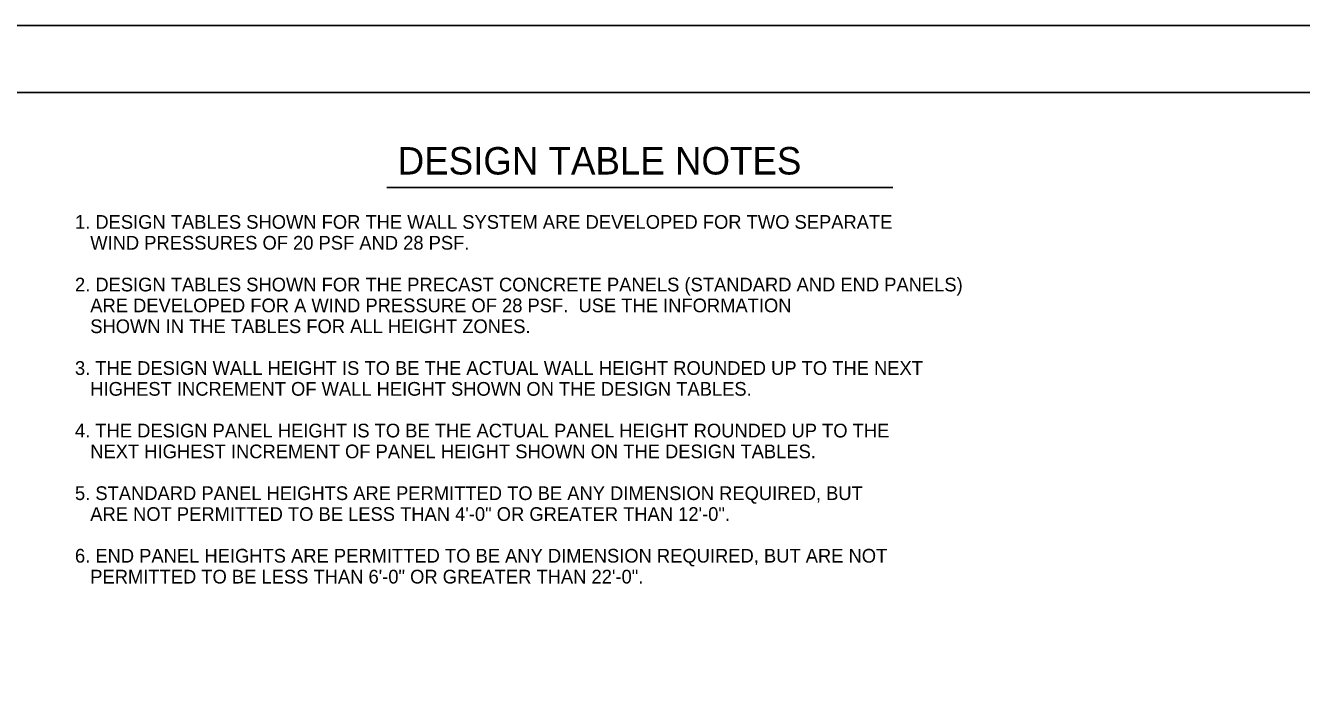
# Model space of a CAD drawing. Extents: x 3385 to 6532, y -616 to 1166.
# Drawn here: x 4106 to 4391.8, y 1016.6 to 1165.7 of the extents above; entities that cross this region are included whole.
import ezdxf

# ---------------------------------------------------------------- set-up
doc = ezdxf.new("R2010")
doc.units = 0
for name, color, linetype in [('1', 7, 'Continuous'), ('2', 7, 'Continuous'), ('PLT-BNDY', 7, 'Continuous')]:
    doc.layers.add(name, color=color, linetype=linetype)

msp = doc.modelspace()

# ---------------------------------------------------------------- linework, layer by layer
at = {"layer": '1'}
msp.add_line((4186.96, 1129.45), (4300.27, 1129.45), dxfattribs=at)
at = {"layer": '2'}
msp.add_line((3801.34, 1150.69), (4587.34, 1150.69), dxfattribs=at)
at = {"layer": 'PLT-BNDY'}
msp.add_lwpolyline([(3761.34, 1165.69), (4602.34, 1165.69), (4602.34, 571.69), (3761.34, 571.69)], close=True, dxfattribs=at)

# ---------------------------------------------------------------- texts
at = {"layer": '1'}
for s, height, p in [('DESIGN TABLE NOTES', 6.1441, (4189.36, 1132.33)), ('1. DESIGN TABLES SHOWN FOR THE WALL SYSTEM ARE DEVELOPED FOR TWO SEPARATE', 3.072, (4117.08, 1120.17)), ('   WIND PRESSURES OF 20 PSF AND 28 PSF.', 3.072, (4117.08, 1115.5)), ('2. DESIGN TABLES SHOWN FOR THE PRECAST CONCRETE PANELS (STANDARD AND END PANELS)', 3.072, (4117.08, 1106.15)), ('   ARE DEVELOPED FOR A WIND PRESSURE OF 28 PSF.  USE THE INFORMATION', 3.072, (4117.08, 1101.48)), ('   SHOWN IN THE TABLES FOR ALL HEIGHT ZONES.', 3.072, (4117.08, 1096.81)), ('3. THE DESIGN WALL HEIGHT IS TO BE THE ACTUAL WALL HEIGHT ROUNDED UP TO THE NEXT', 3.072, (4117.08, 1087.46)), ('   HIGHEST INCREMENT OF WALL HEIGHT SHOWN ON THE DESIGN TABLES.', 3.072, (4117.08, 1082.79)), ('4. THE DESIGN PANEL HEIGHT IS TO BE THE ACTUAL PANEL HEIGHT ROUNDED UP TO THE', 3.072, (4117.08, 1073.45)), ('   NEXT HIGHEST INCREMENT OF PANEL HEIGHT SHOWN ON THE DESIGN TABLES.', 3.072, (4117.08, 1068.78)), ('5. STANDARD PANEL HEIGHTS ARE PERMITTED TO BE ANY DIMENSION REQUIRED, BUT ', 3.072, (4117.08, 1059.43)), ('   ARE NOT PERMITTED TO BE LESS THAN 4\'-0" OR GREATER THAN 12\'-0".', 3.072, (4117.08, 1054.76)), ('6. END PANEL HEIGHTS ARE PERMITTED TO BE ANY DIMENSION REQUIRED, BUT ARE NOT ', 3.072, (4117.08, 1045.42)), ('   PERMITTED TO BE LESS THAN 6\'-0" OR GREATER THAN 22\'-0".', 3.072, (4117.08, 1040.74))]:
    msp.add_text(s, height=height, dxfattribs=at).set_placement(p)

doc.saveas('drawing.dxf')
